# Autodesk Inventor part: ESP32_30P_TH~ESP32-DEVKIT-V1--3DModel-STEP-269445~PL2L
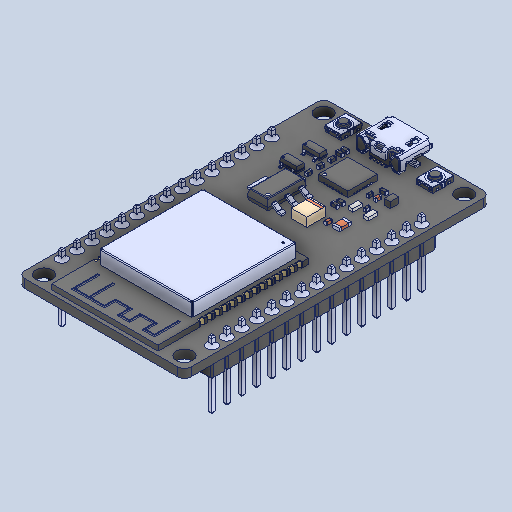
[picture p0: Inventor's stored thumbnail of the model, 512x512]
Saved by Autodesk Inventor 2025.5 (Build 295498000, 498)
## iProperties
Created: 2026-10
Part Number: ESP32_30P_TH~ESP32-DEVKIT-V1--3DModel-STEP-269445~PL2L
Material: Genérico
Document SubType Name: Modeling
Designer: Luis M
Density: 1 g/cm^3
Appearance: Valor por defecto
Author: Luis M
Revision Number: ANY
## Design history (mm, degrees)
feature "board-1-solid1"
feature "board-1-solid2"
feature "board-1-solid3"
feature "board-1-solid4"
feature "board-1-solid5"
feature "board-1-solid6"
feature "board-1-solid7"
feature "board-1-solid8"
feature "board-1-solid9"
feature "board-1-solid10"
feature "board-1-solid11"
feature "board-1-solid12"
feature "board-1-solid13"
feature "board-1-solid14"
feature "board-1-solid15"
feature "board-1-solid16"
feature "board-1-solid17"
feature "board-1-solid18"
feature "board-1-solid19"
feature "board-1-solid20"
feature "board-1-solid21"
feature "board-1-solid22"
feature "board-1-solid23"
feature "board-1-solid24"
feature "board-1-solid25"
feature "board-1-solid26"
feature "board-1-solid27"
feature "board-1-solid28"
feature "board-1-solid29"
feature "board-1-solid30"
feature "board-1-solid31"
feature "header-1-solid1"
feature "header-1-solid2"
feature "header-1-solid3"
feature "header-1-solid4"
feature "header-1-solid5"
feature "header-1-solid6"
feature "header-1-solid7"
feature "header-1-solid8"
feature "header-1-solid9"
feature "header-1-solid10"
feature "header-1-solid11"
feature "header-1-solid12"
feature "header-1-solid13"
feature "header-1-solid14"
feature "header-1-solid15"
feature "header-1-solid16"
feature "header-1-solid17"
feature "header-1-solid18"
feature "header-1-solid19"
feature "header-1-solid20"
feature "header-1-solid21"
feature "header-1-solid22"
feature "header-1-solid23"
feature "header-1-solid24"
feature "header-1-solid25"
feature "header-1-solid26"
feature "header-1-solid27"
feature "header-1-solid28"
feature "header-1-solid29"
feature "header-1-solid30"
feature "header-2-solid1"
feature "header-2-solid2"
feature "header-2-solid3"
feature "header-2-solid4"
feature "header-2-solid5"
feature "header-2-solid6"
feature "header-2-solid7"
feature "header-2-solid8"
feature "header-2-solid9"
feature "header-2-solid10"
feature "header-2-solid11"
feature "header-2-solid12"
feature "header-2-solid13"
feature "header-2-solid14"
feature "header-2-solid15"
feature "header-2-solid16"
feature "header-2-solid17"
feature "header-2-solid18"
feature "header-2-solid19"
feature "header-2-solid20"
feature "header-2-solid21"
feature "header-2-solid22"
feature "header-2-solid23"
feature "header-2-solid24"
feature "header-2-solid25"
feature "header-2-solid26"
feature "header-2-solid27"
feature "header-2-solid28"
feature "header-2-solid29"
feature "header-2-solid30"
feature "ESP32-1-solid1"
feature "ESP32-1-solid2"
feature "ESP32-1-solid3"
feature "ESP32-1-solid4"
feature "ESP32-1-solid5"
feature "ESP32-1-solid6"
feature "ESP32-1-solid7"
feature "ESP32-1-solid8"
feature "ESP32-1-solid9"
feature "ESP32-1-solid10"
feature "ESP32-1-solid11"
feature "ESP32-1-solid12"
feature "ESP32-1-solid13"
feature "ESP32-1-solid14"
feature "ESP32-1-solid15"
feature "ESP32-1-solid16"
feature "ESP32-1-solid17"
feature "ESP32-1-solid18"
feature "ESP32-1-solid19"
feature "ESP32-1-solid20"
feature "ESP32-1-solid21"
feature "ESP32-1-solid22"
feature "ESP32-1-solid23"
feature "ESP32-1-solid24"
feature "ESP32-1-solid25"
feature "ESP32-1-solid26"
feature "ESP32-1-solid27"
feature "ESP32-1-solid28"
feature "ESP32-1-solid29"
feature "ESP32-1-solid30"
feature "ESP32-1-solid31"
feature "ESP32-1-solid32"
feature "ESP32-1-solid33"
feature "ESP32-1-solid34"
feature "ESP32-1-solid35"
feature "ESP32-1-solid36"
feature "ESP32-1-solid37"
feature "ESP32-1-solid38"
feature "ESP32-1-solid39"
feature "ESP32-1-solid40"
feature "ESP32-1-solid41"
feature "micro usb-1-solid1"
feature "micro usb-1-solid2"
feature "micro usb-1-solid3"
feature "micro usb-1-solid4"
feature "micro usb-1-solid5"
feature "micro usb-1-solid6"
feature "micro usb-1-solid7"
feature "micro usb-1-solid8"
feature "micro usb-1-solid9"
feature "micro usb-1-solid10"
feature "micro usb-1-solid11"
feature "micro usb-1-solid12"
feature "micro usb-1-solid13"
feature "micro usb-1-solid14"
feature "micro usb-1-solid15"
feature "micro usb-1-solid16"
feature "micro usb-1-solid17"
feature "button-1-solid1"
feature "button-1-solid2"
feature "button-1-solid3"
feature "button-1-solid4"
feature "button-1-solid5"
feature "button-1-solid6"
feature "button-1-solid7"
feature "button-2-solid1"
feature "button-2-solid2"
feature "button-2-solid3"
feature "button-2-solid4"
feature "button-2-solid5"
feature "button-2-solid6"
feature "button-2-solid7"
feature "AMS1117-3.3-1-solid1"
feature "AMS1117-3.3-1-solid2"
feature "AMS1117-3.3-1-solid3"
feature "AMS1117-3.3-1-solid4"
feature "AMS1117-3.3-1-solid5"
feature "AMS1117-3.3-1-solid6"
feature "CP2102-1-solid1"
feature "CP2102-1-solid2"
feature "CP2102-1-solid3"
feature "CP2102-1-solid4"
feature "CP2102-1-solid5"
feature "CP2102-1-solid6"
feature "CP2102-1-solid7"
feature "CP2102-1-solid8"
feature "CP2102-1-solid9"
feature "CP2102-1-solid10"
feature "CP2102-1-solid11"
feature "CP2102-1-solid12"
feature "CP2102-1-solid13"
feature "CP2102-1-solid14"
feature "CP2102-1-solid15"
feature "CP2102-1-solid16"
feature "CP2102-1-solid17"
feature "CP2102-1-solid18"
feature "CP2102-1-solid19"
feature "CP2102-1-solid20"
feature "CP2102-1-solid21"
feature "CP2102-1-solid22"
feature "CP2102-1-solid23"
feature "CP2102-1-solid24"
feature "CP2102-1-solid25"
feature "CP2102-1-solid26"
feature "CP2102-1-solid27"
feature "CP2102-1-solid28"
feature "CP2102-1-solid29"
feature "CP2102-1-solid30"
feature "CP2102-1-solid31"
feature "sot-23-3-1-solid1"
feature "sot-23-3-1-solid2"
feature "sot-23-3-1-solid3"
feature "sot-23-3-1-solid4"
feature "sot-23-3-1-solid5"
feature "other^ESP32-DEVKIT-V1-1-solid1"
feature "other^ESP32-DEVKIT-V1-1-solid2"
feature "other^ESP32-DEVKIT-V1-1-solid3"
feature "other^ESP32-DEVKIT-V1-1-solid4"
feature "other^ESP32-DEVKIT-V1-1-solid5"
feature "other^ESP32-DEVKIT-V1-1-solid6"
feature "other^ESP32-DEVKIT-V1-1-solid7"
feature "other^ESP32-DEVKIT-V1-1-solid8"
feature "other^ESP32-DEVKIT-V1-1-solid9"
feature "other^ESP32-DEVKIT-V1-1-solid10"
feature "other^ESP32-DEVKIT-V1-1-solid11"
feature "other^ESP32-DEVKIT-V1-1-solid12"
feature "other^ESP32-DEVKIT-V1-1-solid13"
feature "other^ESP32-DEVKIT-V1-1-solid14"
feature "other^ESP32-DEVKIT-V1-1-solid15"
feature "other^ESP32-DEVKIT-V1-1-solid16"
feature "other^ESP32-DEVKIT-V1-1-solid17"
feature "other^ESP32-DEVKIT-V1-1-solid18"
feature "other^ESP32-DEVKIT-V1-1-solid19"
feature "other^ESP32-DEVKIT-V1-1-solid20"
feature "other^ESP32-DEVKIT-V1-1-solid21"
feature "other^ESP32-DEVKIT-V1-1-solid22"
feature "other^ESP32-DEVKIT-V1-1-solid23"
feature "other^ESP32-DEVKIT-V1-1-solid24"
feature "other^ESP32-DEVKIT-V1-1-solid25"
feature "other^ESP32-DEVKIT-V1-1-solid26"
feature "other^ESP32-DEVKIT-V1-1-solid27"
feature "other^ESP32-DEVKIT-V1-1-solid28"
feature "other^ESP32-DEVKIT-V1-1-solid29"
feature "other^ESP32-DEVKIT-V1-1-solid30"
feature "other^ESP32-DEVKIT-V1-1-solid31"
feature "other^ESP32-DEVKIT-V1-1-solid32"
feature "other^ESP32-DEVKIT-V1-1-solid33"
feature "other^ESP32-DEVKIT-V1-1-solid34"
feature "other^ESP32-DEVKIT-V1-1-solid35"
feature "other^ESP32-DEVKIT-V1-1-solid36"
feature "other^ESP32-DEVKIT-V1-1-solid37"
feature "other^ESP32-DEVKIT-V1-1-solid38"
feature "other^ESP32-DEVKIT-V1-1-solid39"
feature "other^ESP32-DEVKIT-V1-1-solid40"
feature "other^ESP32-DEVKIT-V1-1-solid41"
feature "other^ESP32-DEVKIT-V1-1-solid42"
feature "other^ESP32-DEVKIT-V1-1-solid43"
feature "other^ESP32-DEVKIT-V1-1-solid44"
feature "other^ESP32-DEVKIT-V1-1-solid45"
feature "other^ESP32-DEVKIT-V1-1-solid46"
feature "other^ESP32-DEVKIT-V1-1-solid47"
feature "sot-23-3-3-solid1"
feature "sot-23-3-3-solid2"
feature "sot-23-3-3-solid3"
feature "sot-23-3-3-solid4"
feature "sot-23-3-3-solid5"
node "Sólido1"
node "Sólido2"
node "Sólido3"
node "Sólido4"
node "Sólido5"
node "Sólido6"
node "Sólido7"
node "Sólido8"
node "Sólido9"
node "Sólido10"
node "Sólido11"
node "Sólido12"
node "Sólido13"
node "Sólido14"
node "Sólido15"
node "Sólido16"
node "Sólido17"
node "Sólido18"
node "Sólido19"
node "Sólido20"
node "Sólido21"
node "Sólido22"
node "Sólido23"
node "Sólido24"
node "Sólido25"
node "Sólido26"
node "Sólido27"
node "Sólido28"
node "Sólido29"
node "Sólido30"
node "Sólido31"
node "Sólido32"
node "Sólido33"
node "Sólido34"
node "Sólido35"
node "Sólido36"
node "Sólido37"
node "Sólido38"
node "Sólido39"
node "Sólido40"
node "Sólido41"
node "Sólido42"
node "Sólido43"
node "Sólido44"
node "Sólido45"
node "Sólido46"
node "Sólido47"
node "Sólido48"
node "Sólido49"
node "Sólido50"
node "Sólido51"
node "Sólido52"
node "Sólido53"
node "Sólido54"
node "Sólido55"
node "Sólido56"
node "Sólido57"
node "Sólido58"
node "Sólido59"
node "Sólido60"
node "Sólido61"
node "Sólido62"
node "Sólido63"
node "Sólido64"
node "Sólido65"
node "Sólido66"
node "Sólido67"
node "Sólido68"
node "Sólido69"
node "Sólido70"
node "Sólido71"
node "Sólido72"
node "Sólido73"
node "Sólido74"
node "Sólido75"
node "Sólido76"
node "Sólido77"
node "Sólido78"
node "Sólido79"
node "Sólido80"
node "Sólido81"
node "Sólido82"
node "Sólido83"
node "Sólido84"
node "Sólido85"
node "Sólido86"
node "Sólido87"
node "Sólido88"
node "Sólido89"
node "Sólido90"
node "Sólido91"
node "Sólido92"
node "Sólido93"
node "Sólido94"
node "Sólido95"
node "Sólido96"
node "Sólido97"
node "Sólido98"
node "Sólido99"
node "Sólido100"
node "Sólido101"
node "Sólido102"
node "Sólido103"
node "Sólido104"
node "Sólido105"
node "Sólido106"
node "Sólido107"
node "Sólido108"
node "Sólido109"
node "Sólido110"
node "Sólido111"
node "Sólido112"
node "Sólido113"
node "Sólido114"
node "Sólido115"
node "Sólido116"
node "Sólido117"
node "Sólido118"
node "Sólido119"
node "Sólido120"
node "Sólido121"
node "Sólido122"
node "Sólido123"
node "Sólido124"
node "Sólido125"
node "Sólido126"
node "Sólido127"
node "Sólido128"
node "Sólido129"
node "Sólido130"
node "Sólido131"
node "Sólido132"
node "Sólido133"
node "Sólido134"
node "Sólido135"
node "Sólido136"
node "Sólido137"
node "Sólido138"
node "Sólido139"
node "Sólido140"
node "Sólido141"
node "Sólido142"
node "Sólido143"
node "Sólido144"
node "Sólido145"
node "Sólido146"
node "Sólido147"
node "Sólido148"
node "Sólido149"
node "Sólido150"
node "Sólido151"
node "Sólido152"
node "Sólido153"
node "Sólido154"
node "Sólido155"
node "Sólido156"
node "Sólido157"
node "Sólido158"
node "Sólido159"
node "Sólido160"
node "Sólido161"
node "Sólido162"
node "Sólido163"
node "Sólido164"
node "Sólido165"
node "Sólido166"
node "Sólido167"
node "Sólido168"
node "Sólido169"
node "Sólido170"
node "Sólido171"
node "Sólido172"
node "Sólido173"
node "Sólido174"
node "Sólido175"
node "Sólido176"
node "Sólido177"
node "Sólido178"
node "Sólido179"
node "Sólido180"
node "Sólido181"
node "Sólido182"
node "Sólido183"
node "Sólido184"
node "Sólido185"
node "Sólido186"
node "Sólido187"
node "Sólido188"
node "Sólido189"
node "Sólido190"
node "Sólido191"
node "Sólido192"
node "Sólido193"
node "Sólido194"
node "Sólido195"
node "Sólido196"
node "Sólido197"
node "Sólido198"
node "Sólido199"
node "Sólido200"
node "Sólido201"
node "Sólido202"
node "Sólido203"
node "Sólido204"
node "Sólido205"
node "Sólido206"
node "Sólido207"
node "Sólido208"
node "Sólido209"
node "Sólido210"
node "Sólido211"
node "Sólido212"
node "Sólido213"
node "Sólido214"
node "Sólido215"
node "Sólido216"
node "Sólido217"
node "Sólido218"
node "Sólido219"
node "Sólido220"
node "Sólido221"
node "Sólido222"
node "Sólido223"
node "Sólido224"
node "Sólido225"
node "Sólido226"
node "Sólido227"
node "Sólido228"
node "Sólido229"
node "Sólido230"
node "Sólido231"
node "Sólido232"
node "Sólido233"
node "Sólido234"
node "Sólido235"
node "Sólido236"
node "Sólido237"
node "Sólido238"
node "Sólido239"
node "Sólido240"
node "Sólido241"
node "Sólido242"
node "Sólido243"
node "Sólido244"
node "Sólido245"
node "Sólido246"
node "Sólido247"
node "Sólido248"
node "Sólido249"
node "Sólido250"
node "Sólido251"
node "Sólido252"
node "Sólido253"
node "Sólido254"
node "Sólido255"
node "Sólido256"
node "Sólido257"
